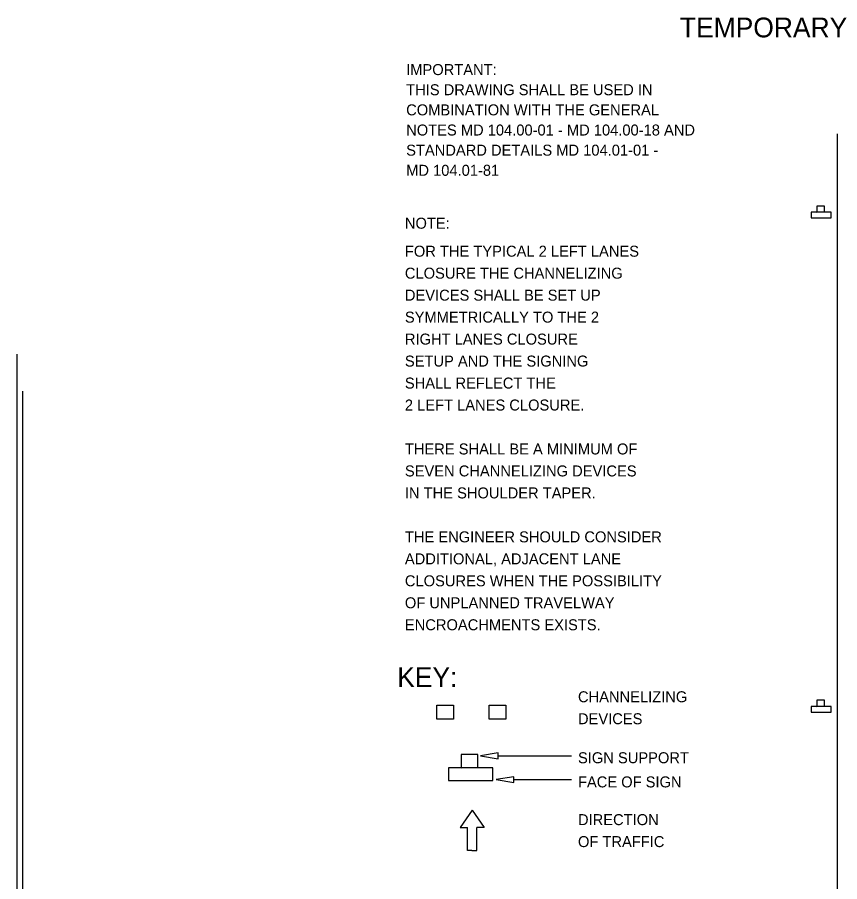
# Model space of a CAD drawing. Extents: x 15310.1 to 15319.5, y 15309 to 15319.1.
# Drawn here: x 15310.134 to 15314.628, y 15314.35 to 15319.071 of the extents above; entities that cross this region are included whole.
import ezdxf

# ---------------------------------------------------------------- set-up
doc = ezdxf.new("R2010")
doc.units = 0
for name, color, linetype in [('DETL-DIMS', 7, 'Continuous'), ('DETL-LINE', 7, 'Continuous'), ('DETL-NOTE', 7, 'Continuous'), ('DETL-TITL', 7, 'Continuous'), ('USER-BORD', 7, 'Continuous')]:
    doc.layers.add(name, color=color, linetype=linetype)

# ---------------------------------------------------------------- blocks, each defined once
blk = doc.blocks.new('DIR4')
at = {"layer": 'USER-BORD'}
for p, q in [((0, 0.001), (-0.034, -0.048)), ((0, 0.001), (0.034, -0.048)), ((-0.034, -0.048), (-0.013, -0.048)), ((-0.013, -0.113), (-0.013, -0.048)), ((0.034, -0.048), (0.013, -0.048)), ((0.013, -0.113), (0.013, -0.048)), ((-0.001, -0.113), (-0.013, -0.113)), ((-0.001, -0.113), (0.001, -0.113)), ((0.001, -0.113), (0.013, -0.113))]:
    blk.add_line(p, q, dxfattribs=at)
blk = doc.blocks.new('SIGN15')
at = {"layer": 'USER-BORD'}
for points in [[(-0.013, 0.018), (0.011, 0.019), (0.011, 0.037), (-0.013, 0.037)], [(-0.031, 0.018), (-0.031, 0), (0.032, 0), (0.032, 0.018)]]:
    blk.add_lwpolyline(points, close=True, dxfattribs=at)

msp = doc.modelspace()

# ---------------------------------------------------------------- linework, layer by layer
at = {"layer": 'DETL-DIMS'}
for p, q in [((15312.761, 15315.037), (15313.163, 15315.037)), ((15312.847, 15314.908), (15313.163, 15314.908))]:
    msp.add_line(p, q, dxfattribs=at)
for points in [[(15312.761, 15315.021), (15312.761, 15315.054), (15312.665, 15315.037)], [(15312.847, 15314.892), (15312.847, 15314.923), (15312.751, 15314.908)]]:
    msp.add_lwpolyline(points, close=True, dxfattribs=at)
at = {"layer": 'DETL-LINE'}
for p, q in [((15314.614, 15318.4337), (15314.614, 15310.79)), ((15310.1336, 15309.5875), (15310.1336, 15317.2313)), ((15310.1637, 15309.3853), (15310.1637, 15317.0291))]:
    msp.add_line(p, q, dxfattribs=at)
for points in [[(15312.426, 15315.237), (15312.426, 15315.315), (15312.518, 15315.315), (15312.518, 15315.237)], [(15312.713, 15315.237), (15312.713, 15315.315), (15312.804, 15315.315), (15312.804, 15315.237)]]:
    msp.add_lwpolyline(points, close=True, dxfattribs=at)

# ---------------------------------------------------------------- block references
for name, p, xscale, yscale in [('SIGN15', (15314.526, 15317.975), 1.7523809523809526, 1.7523809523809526), ('SIGN15', (15314.526, 15315.276), 1.7523809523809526, 1.7523809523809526), ('SIGN15', (15312.609, 15314.903), 3.8400000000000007, 3.8400000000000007), ('DIR4', (15312.62, 15314.738), 1.9200000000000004, 1.9200000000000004)]:
    msp.add_blockref(name, p, dxfattribs=dict(at, xscale=xscale, yscale=yscale))

# ---------------------------------------------------------------- texts
at = {"layer": 'DETL-NOTE'}
for s, p in [('IMPORTANT:', (15312.259, 15318.755)), ('THIS DRAWING SHALL BE USED IN', (15312.259, 15318.645)), ('COMBINATION WITH THE GENERAL', (15312.259, 15318.535)), ('NOTES MD 104.00-01 - MD 104.00-18 AND', (15312.259, 15318.425)), ('STANDARD DETAILS MD 104.01-01 -', (15312.259, 15318.315)), ('MD 104.01-81', (15312.259, 15318.205)), ('NOTE:', (15312.252, 15317.916)), ('FOR THE TYPICAL 2 LEFT LANES', (15312.252, 15317.7632)), ('CLOSURE THE CHANNELIZING', (15312.252, 15317.6432)), ('DEVICES SHALL BE SET UP', (15312.252, 15317.5232)), ('SYMMETRICALLY TO THE 2', (15312.252, 15317.4032)), ('RIGHT LANES CLOSURE', (15312.252, 15317.2832)), ('SETUP AND THE SIGNING', (15312.252, 15317.1632)), ('SHALL REFLECT THE', (15312.252, 15317.0432)), ('2 LEFT LANES CLOSURE.', (15312.252, 15316.9232)), ('THERE SHALL BE A MINIMUM OF ', (15312.252, 15316.6832)), ('SEVEN CHANNELIZING DEVICES ', (15312.252, 15316.5632)), ('IN THE SHOULDER TAPER.', (15312.252, 15316.4432)), ('THE ENGINEER SHOULD CONSIDER', (15312.252, 15316.2032)), ('ADDITIONAL, ADJACENT LANE', (15312.252, 15316.0832)), ('CLOSURES WHEN THE POSSIBILITY', (15312.252, 15315.9632)), ('OF UNPLANNED TRAVELWAY', (15312.252, 15315.8432)), ('ENCROACHMENTS EXISTS.', (15312.252, 15315.7232)), ('CHANNELIZING', (15313.198, 15315.33)), ('DEVICES', (15313.198, 15315.21)), ('SIGN SUPPORT', (15313.198, 15314.997)), ('FACE OF SIGN', (15313.198, 15314.865)), ('DIRECTION', (15313.198, 15314.659)), ('OF TRAFFIC', (15313.198, 15314.539))]:
    msp.add_text(s, height=0.06, dxfattribs=at).set_placement(p)
at = {"layer": 'DETL-TITL'}
for s, p in [('TEMPORARY TRAFFIC CONTROL TYPICAL APPLICATION ', (15313.755, 15318.961)), ('KEY:', (15312.21, 15315.413))]:
    msp.add_text(s, height=0.108, dxfattribs=at).set_placement(p)

doc.saveas('drawing.dxf')
